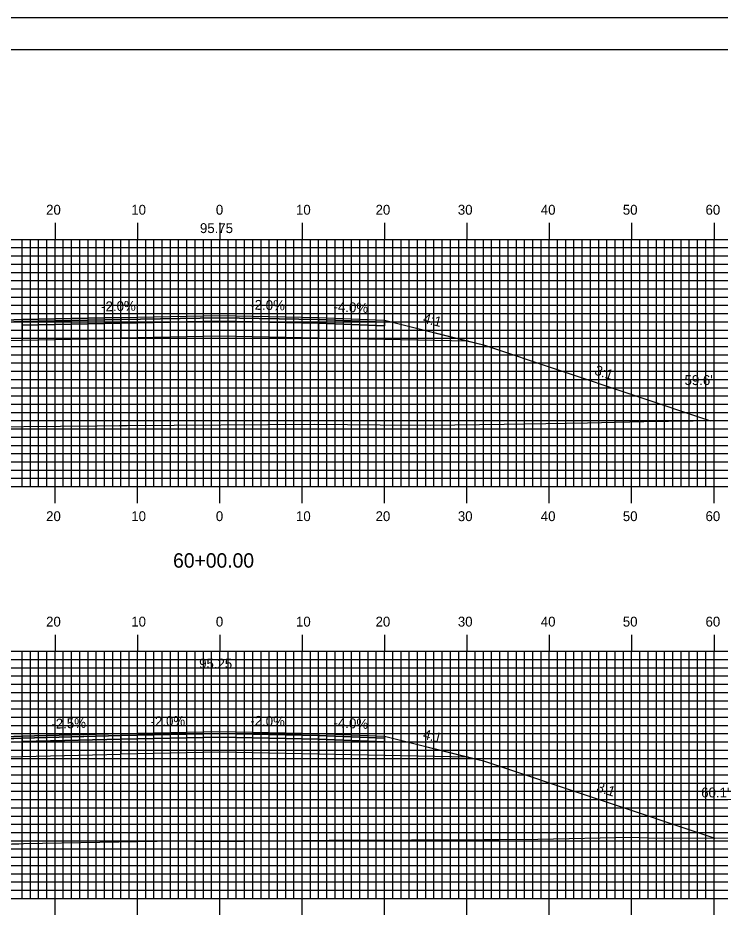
# Model space of a CAD drawing. Extents: x 1757462 to 1757806, y 442591 to 442811.
# Drawn here: x 1757603.6 to 1757689, y 442701.2 to 442810.5 of the extents above; entities that cross this region are included whole.
import ezdxf

# ---------------------------------------------------------------- set-up
doc = ezdxf.new("R2010")
doc.units = 0
for name, color, linetype in [('ANNOTATION', 7, 'Continuous'), ('BORDER', 7, 'Continuous'), ('D_Roadway_Centerline', 7, 'Continuous'), ('D_Roadway_Centerline_Text', 7, 'Continuous'), ('D_Roadway_Edge_Shoulder', 7, 'Continuous'), ('D_Roadway_Edge_TW', 7, 'Continuous'), ('D_Roadway_Pavement', 7, 'Continuous'), ('D_Roadway_SlopeLines', 7, 'Continuous'), ('D_Roadway_SubGrade', 7, 'Continuous'), ('D_Text_Standard', 7, 'Continuous'), ('H_V ANNOTATION', 7, 'Continuous'), ('MAJOR', 7, 'Continuous'), ('MINOR', 7, 'Continuous'), ('PLOT BOUNDARY', 7, 'Continuous'), ('S_Roadway_Centerline', 7, 'Continuous')]:
    doc.layers.add(name, color=color, linetype=linetype)

msp = doc.modelspace()

# ---------------------------------------------------------------- linework, layer by layer
at = {"layer": 'BORDER'}
msp.add_lwpolyline([(1757478.51, 442596.67), (1757798.51, 442596.67), (1757798.51, 442806.67), (1757478.51, 442806.67)], close=True, dxfattribs=at)
at = {"layer": 'D_Roadway_Centerline'}
for points in [[(1757554.49, 442760.74), (1757584.11, 442770.62), (1757585.94, 442771.07), (1757596.11, 442773.62), (1757604.11, 442773.94), (1757616.11, 442774.18), (1757628.11, 442774.42), (1757640.11, 442774.18), (1757648.11, 442773.86), (1757658.28, 442771.31), (1757660.11, 442770.86), (1757687.69, 442761.66)], [(1757552.67, 442709.58), (1757584.11, 442720.06), (1757585.55, 442720.42), (1757596.11, 442723.06), (1757604.11, 442723.38), (1757616.11, 442723.68), (1757628.11, 442723.92), (1757640.11, 442723.68), (1757648.11, 442723.36), (1757658.28, 442720.81), (1757660.11, 442720.36), (1757688.21, 442710.99)]]:
    msp.add_lwpolyline(points, dxfattribs=at)
at = {"layer": 'D_Roadway_Edge_Shoulder'}
for points in [[(1757604.11, 442773.94), (1757596.11, 442773.62), (1757596.11, 442773.37), (1757604.11, 442773.69)], [(1757640.11, 442774.18), (1757648.11, 442773.86), (1757648.11, 442773.61), (1757640.11, 442773.93)], [(1757604.11, 442723.38), (1757596.11, 442723.06), (1757596.11, 442722.81), (1757604.11, 442723.13)], [(1757640.11, 442723.68), (1757648.11, 442723.36), (1757648.11, 442723.11), (1757640.11, 442723.43)]]:
    msp.add_lwpolyline(points, close=True, dxfattribs=at)
at = {"layer": 'D_Roadway_Edge_TW'}
for points in [[(1757616.11, 442773.93), (1757616.11, 442774.18), (1757628.11, 442774.42), (1757640.11, 442774.18), (1757640.11, 442773.93), (1757628.11, 442774.17)], [(1757616.11, 442774.18), (1757604.11, 442773.94), (1757604.11, 442773.69), (1757616.11, 442773.93)], [(1757616.11, 442723.68), (1757604.11, 442723.38), (1757604.11, 442723.13), (1757616.11, 442723.43)], [(1757616.11, 442723.43), (1757616.11, 442723.68), (1757628.11, 442723.92), (1757640.11, 442723.68), (1757640.11, 442723.43), (1757628.11, 442723.67)]]:
    msp.add_lwpolyline(points, close=True, dxfattribs=at)
for points in [[(1757616.11, 442774.18), (1757616.11, 442773.93)], [(1757616.11, 442723.68), (1757616.11, 442723.43)]]:
    msp.add_lwpolyline(points, dxfattribs=at)
at = {"layer": 'D_Roadway_Pavement'}
for points in [[(1757616.11, 442773.93), (1757604.11, 442773.69), (1757604.11, 442773.27), (1757616.11, 442773.51)], [(1757616.11, 442773.51), (1757616.11, 442773.93), (1757628.11, 442774.17), (1757640.11, 442773.93), (1757640.11, 442773.51), (1757628.11, 442773.75)], [(1757640.11, 442773.93), (1757648.11, 442773.61), (1757648.11, 442773.19), (1757640.11, 442773.51)], [(1757616.11, 442723.43), (1757604.11, 442723.13), (1757604.11, 442722.71), (1757616.11, 442723.01)], [(1757616.11, 442723.01), (1757616.11, 442723.43), (1757628.11, 442723.67), (1757640.11, 442723.43), (1757640.11, 442723.01), (1757628.11, 442723.25)], [(1757640.11, 442723.43), (1757648.11, 442723.11), (1757648.11, 442722.69), (1757640.11, 442723.01)]]:
    msp.add_lwpolyline(points, close=True, dxfattribs=at)
for points in [[(1757604.11, 442773.69), (1757604.11, 442773.27)], [(1757616.11, 442773.93), (1757616.11, 442773.51)], [(1757616.11, 442773.93), (1757616.11, 442773.51)], [(1757604.11, 442723.13), (1757604.11, 442722.71)], [(1757616.11, 442723.43), (1757616.11, 442723.01)], [(1757616.11, 442723.43), (1757616.11, 442723.01)]]:
    msp.add_lwpolyline(points, dxfattribs=at)
at = {"layer": 'D_Roadway_SlopeLines'}
for points in [[(1757648.11, 442773.86), (1757660.11, 442770.86), (1757687.69, 442761.66)], [(1757648.11, 442723.36), (1757660.11, 442720.36), (1757688.21, 442710.99)]]:
    msp.add_lwpolyline(points, dxfattribs=at)
at = {"layer": 'D_Roadway_SubGrade'}
for points in [[(1757604.11, 442773.27), (1757604.11, 442773.69), (1757596.11, 442773.37), (1757596.11, 442773.62), (1757585.94, 442771.07), (1757604.11, 442771.44)], [(1757616.11, 442773.51), (1757604.11, 442773.27), (1757604.11, 442771.44), (1757616.11, 442771.68)], [(1757616.11, 442771.68), (1757616.11, 442773.51), (1757628.11, 442773.75), (1757640.11, 442773.51), (1757640.11, 442771.68), (1757628.11, 442771.92)], [(1757640.11, 442773.51), (1757648.11, 442773.19), (1757648.11, 442773.61), (1757648.11, 442773.86), (1757658.28, 442771.31), (1757640.11, 442771.68)], [(1757604.11, 442722.71), (1757604.11, 442723.13), (1757596.11, 442722.81), (1757596.11, 442723.06), (1757585.55, 442720.42), (1757604.11, 442720.88)], [(1757616.11, 442723.01), (1757604.11, 442722.71), (1757604.11, 442720.88), (1757616.11, 442721.18)], [(1757616.11, 442721.18), (1757616.11, 442723.01), (1757628.11, 442723.25), (1757640.11, 442723.01), (1757640.11, 442721.18), (1757628.11, 442721.42)], [(1757640.11, 442723.01), (1757648.11, 442722.69), (1757648.11, 442723.11), (1757648.11, 442723.36), (1757658.28, 442720.81), (1757640.11, 442721.18)]]:
    msp.add_lwpolyline(points, close=True, dxfattribs=at)
for points in [[(1757616.11, 442773.51), (1757616.11, 442771.68)], [(1757616.11, 442723.01), (1757616.11, 442721.18)]]:
    msp.add_lwpolyline(points, dxfattribs=at)
at = {"layer": 'MAJOR'}
for p, q in [((1757608.11, 442785.67), (1757608.11, 442783.67)), ((1757618.11, 442785.67), (1757618.11, 442783.67)), ((1757628.11, 442785.67), (1757628.11, 442783.67)), ((1757638.11, 442785.67), (1757638.11, 442783.67)), ((1757648.11, 442785.67), (1757648.11, 442783.67)), ((1757658.11, 442785.67), (1757658.11, 442783.67)), ((1757668.11, 442785.67), (1757668.11, 442783.67)), ((1757678.11, 442785.67), (1757678.11, 442783.67)), ((1757688.11, 442785.67), (1757688.11, 442783.67)), ((1757488.11, 442783.67), (1757768.11, 442783.67)), ((1757488.11, 442783.67), (1757768.11, 442783.67)), ((1757608.11, 442753.67), (1757608.11, 442783.67)), ((1757618.11, 442753.67), (1757618.11, 442783.67)), ((1757628.11, 442753.67), (1757628.11, 442783.67)), ((1757638.11, 442753.67), (1757638.11, 442783.67)), ((1757648.11, 442753.67), (1757648.11, 442783.67)), ((1757658.11, 442753.67), (1757658.11, 442783.67)), ((1757668.11, 442753.67), (1757668.11, 442783.67)), ((1757678.11, 442753.67), (1757678.11, 442783.67)), ((1757688.11, 442753.67), (1757688.11, 442783.67)), ((1757488.11, 442778.67), (1757768.11, 442778.67)), ((1757488.11, 442773.67), (1757768.11, 442773.67)), ((1757488.11, 442768.67), (1757768.11, 442768.67)), ((1757488.11, 442763.67), (1757768.11, 442763.67)), ((1757488.11, 442758.67), (1757768.11, 442758.67)), ((1757488.11, 442753.67), (1757768.11, 442753.67)), ((1757488.11, 442753.67), (1757768.11, 442753.67)), ((1757608.11, 442751.66), (1757608.11, 442753.67)), ((1757618.11, 442751.66), (1757618.11, 442753.67)), ((1757628.11, 442751.66), (1757628.11, 442753.67)), ((1757638.11, 442751.66), (1757638.11, 442753.67)), ((1757648.11, 442751.66), (1757648.11, 442753.67)), ((1757658.11, 442751.66), (1757658.11, 442753.67)), ((1757668.11, 442751.66), (1757668.11, 442753.67)), ((1757678.11, 442751.66), (1757678.11, 442753.67)), ((1757688.11, 442751.66), (1757688.11, 442753.67)), ((1757608.11, 442735.67), (1757608.11, 442733.67)), ((1757618.11, 442735.67), (1757618.11, 442733.67)), ((1757628.11, 442735.67), (1757628.11, 442733.67)), ((1757638.11, 442735.67), (1757638.11, 442733.67)), ((1757648.11, 442735.67), (1757648.11, 442733.67)), ((1757658.11, 442735.67), (1757658.11, 442733.67)), ((1757668.11, 442735.67), (1757668.11, 442733.67)), ((1757678.11, 442735.67), (1757678.11, 442733.67)), ((1757688.11, 442735.67), (1757688.11, 442733.67)), ((1757488.11, 442733.67), (1757768.11, 442733.67)), ((1757488.11, 442733.67), (1757768.11, 442733.67)), ((1757608.11, 442703.67), (1757608.11, 442733.67)), ((1757618.11, 442703.67), (1757618.11, 442733.67)), ((1757628.11, 442703.67), (1757628.11, 442733.67)), ((1757638.11, 442703.67), (1757638.11, 442733.67)), ((1757648.11, 442703.67), (1757648.11, 442733.67)), ((1757658.11, 442703.67), (1757658.11, 442733.67)), ((1757668.11, 442703.67), (1757668.11, 442733.67)), ((1757678.11, 442703.67), (1757678.11, 442733.67)), ((1757688.11, 442703.67), (1757688.11, 442733.67)), ((1757488.11, 442728.67), (1757768.11, 442728.67)), ((1757488.11, 442723.67), (1757768.11, 442723.67)), ((1757488.11, 442718.67), (1757768.11, 442718.67)), ((1757488.11, 442713.67), (1757768.11, 442713.67)), ((1757488.11, 442708.67), (1757768.11, 442708.67)), ((1757488.11, 442703.67), (1757768.11, 442703.67)), ((1757488.11, 442703.67), (1757768.11, 442703.67)), ((1757608.11, 442701.66), (1757608.11, 442703.67)), ((1757618.11, 442701.66), (1757618.11, 442703.67)), ((1757628.11, 442701.66), (1757628.11, 442703.67)), ((1757638.11, 442701.66), (1757638.11, 442703.67)), ((1757648.11, 442701.66), (1757648.11, 442703.67)), ((1757658.11, 442701.66), (1757658.11, 442703.67)), ((1757668.11, 442701.66), (1757668.11, 442703.67)), ((1757678.11, 442701.66), (1757678.11, 442703.67)), ((1757688.11, 442701.66), (1757688.11, 442703.67))]:
    msp.add_line(p, q, dxfattribs=at)
at = {"layer": 'MINOR'}
for p, q in [((1757604.11, 442753.67), (1757604.11, 442783.67)), ((1757605.11, 442753.67), (1757605.11, 442783.67)), ((1757606.11, 442753.67), (1757606.11, 442783.67)), ((1757607.11, 442753.67), (1757607.11, 442783.67)), ((1757609.11, 442753.67), (1757609.11, 442783.67)), ((1757610.11, 442753.67), (1757610.11, 442783.67)), ((1757611.11, 442753.67), (1757611.11, 442783.67)), ((1757612.11, 442753.67), (1757612.11, 442783.67)), ((1757613.11, 442753.67), (1757613.11, 442783.67)), ((1757614.11, 442753.67), (1757614.11, 442783.67)), ((1757615.11, 442753.67), (1757615.11, 442783.67)), ((1757616.11, 442753.67), (1757616.11, 442783.67)), ((1757617.11, 442753.67), (1757617.11, 442783.67)), ((1757619.11, 442753.67), (1757619.11, 442783.67)), ((1757620.11, 442753.67), (1757620.11, 442783.67)), ((1757621.11, 442753.67), (1757621.11, 442783.67)), ((1757622.11, 442753.67), (1757622.11, 442783.67)), ((1757623.11, 442753.67), (1757623.11, 442783.67)), ((1757624.11, 442753.67), (1757624.11, 442783.67)), ((1757625.11, 442753.67), (1757625.11, 442783.67)), ((1757626.11, 442753.67), (1757626.11, 442783.67)), ((1757627.11, 442753.67), (1757627.11, 442783.67)), ((1757629.11, 442753.67), (1757629.11, 442783.67)), ((1757630.11, 442753.67), (1757630.11, 442783.67)), ((1757631.11, 442753.67), (1757631.11, 442783.67)), ((1757632.11, 442753.67), (1757632.11, 442783.67)), ((1757633.11, 442753.67), (1757633.11, 442783.67)), ((1757634.11, 442753.67), (1757634.11, 442783.67)), ((1757635.11, 442753.67), (1757635.11, 442783.67)), ((1757636.11, 442753.67), (1757636.11, 442783.67)), ((1757637.11, 442753.67), (1757637.11, 442783.67)), ((1757639.11, 442753.67), (1757639.11, 442783.67)), ((1757640.11, 442753.67), (1757640.11, 442783.67)), ((1757641.11, 442753.67), (1757641.11, 442783.67)), ((1757642.11, 442753.67), (1757642.11, 442783.67)), ((1757643.11, 442753.67), (1757643.11, 442783.67)), ((1757644.11, 442753.67), (1757644.11, 442783.67)), ((1757645.11, 442753.67), (1757645.11, 442783.67)), ((1757646.11, 442753.67), (1757646.11, 442783.67)), ((1757647.11, 442753.67), (1757647.11, 442783.67)), ((1757649.11, 442753.67), (1757649.11, 442783.67)), ((1757650.11, 442753.67), (1757650.11, 442783.67)), ((1757651.11, 442753.67), (1757651.11, 442783.67)), ((1757652.11, 442753.67), (1757652.11, 442783.67)), ((1757653.11, 442753.67), (1757653.11, 442783.67)), ((1757654.11, 442753.67), (1757654.11, 442783.67)), ((1757655.11, 442753.67), (1757655.11, 442783.67)), ((1757656.11, 442753.67), (1757656.11, 442783.67)), ((1757657.11, 442753.67), (1757657.11, 442783.67)), ((1757659.11, 442753.67), (1757659.11, 442783.67)), ((1757660.11, 442753.67), (1757660.11, 442783.67)), ((1757661.11, 442753.67), (1757661.11, 442783.67)), ((1757662.11, 442753.67), (1757662.11, 442783.67)), ((1757663.11, 442753.67), (1757663.11, 442783.67)), ((1757664.11, 442753.67), (1757664.11, 442783.67)), ((1757665.11, 442753.67), (1757665.11, 442783.67)), ((1757666.11, 442753.67), (1757666.11, 442783.67)), ((1757667.11, 442753.67), (1757667.11, 442783.67)), ((1757669.11, 442753.67), (1757669.11, 442783.67)), ((1757670.11, 442753.67), (1757670.11, 442783.67)), ((1757671.11, 442753.67), (1757671.11, 442783.67)), ((1757672.11, 442753.67), (1757672.11, 442783.67)), ((1757673.11, 442753.67), (1757673.11, 442783.67)), ((1757674.11, 442753.67), (1757674.11, 442783.67)), ((1757675.11, 442753.67), (1757675.11, 442783.67)), ((1757676.11, 442753.67), (1757676.11, 442783.67)), ((1757677.11, 442753.67), (1757677.11, 442783.67)), ((1757679.11, 442753.67), (1757679.11, 442783.67)), ((1757680.11, 442753.67), (1757680.11, 442783.67)), ((1757681.11, 442753.67), (1757681.11, 442783.67)), ((1757682.11, 442753.67), (1757682.11, 442783.67)), ((1757683.11, 442753.67), (1757683.11, 442783.67)), ((1757684.11, 442753.67), (1757684.11, 442783.67)), ((1757685.11, 442753.67), (1757685.11, 442783.67)), ((1757686.11, 442753.67), (1757686.11, 442783.67)), ((1757687.11, 442753.67), (1757687.11, 442783.67)), ((1757488.11, 442782.67), (1757768.11, 442782.67)), ((1757488.11, 442781.67), (1757768.11, 442781.67)), ((1757488.11, 442780.67), (1757768.11, 442780.67)), ((1757488.11, 442779.67), (1757768.11, 442779.67)), ((1757488.11, 442777.67), (1757768.11, 442777.67)), ((1757488.11, 442776.67), (1757768.11, 442776.67)), ((1757488.11, 442775.67), (1757768.11, 442775.67)), ((1757488.11, 442774.67), (1757768.11, 442774.67)), ((1757488.11, 442772.67), (1757768.11, 442772.67)), ((1757488.11, 442771.67), (1757768.11, 442771.67)), ((1757488.11, 442770.67), (1757768.11, 442770.67)), ((1757488.11, 442769.67), (1757768.11, 442769.67)), ((1757488.11, 442767.67), (1757768.11, 442767.67)), ((1757488.11, 442766.67), (1757768.11, 442766.67)), ((1757488.11, 442765.67), (1757768.11, 442765.67)), ((1757488.11, 442764.67), (1757768.11, 442764.67)), ((1757488.11, 442762.67), (1757768.11, 442762.67)), ((1757488.11, 442761.67), (1757768.11, 442761.67)), ((1757488.11, 442760.67), (1757768.11, 442760.67)), ((1757488.11, 442759.67), (1757768.11, 442759.67)), ((1757488.11, 442757.67), (1757768.11, 442757.67)), ((1757488.11, 442756.67), (1757768.11, 442756.67)), ((1757488.11, 442755.67), (1757768.11, 442755.67)), ((1757488.11, 442754.67), (1757768.11, 442754.67)), ((1757604.11, 442703.67), (1757604.11, 442733.67)), ((1757605.11, 442703.67), (1757605.11, 442733.67)), ((1757606.11, 442703.67), (1757606.11, 442733.67)), ((1757607.11, 442703.67), (1757607.11, 442733.67)), ((1757609.11, 442703.67), (1757609.11, 442733.67)), ((1757610.11, 442703.67), (1757610.11, 442733.67)), ((1757611.11, 442703.67), (1757611.11, 442733.67)), ((1757612.11, 442703.67), (1757612.11, 442733.67)), ((1757613.11, 442703.67), (1757613.11, 442733.67)), ((1757614.11, 442703.67), (1757614.11, 442733.67)), ((1757615.11, 442703.67), (1757615.11, 442733.67)), ((1757616.11, 442703.67), (1757616.11, 442733.67)), ((1757617.11, 442703.67), (1757617.11, 442733.67)), ((1757619.11, 442703.67), (1757619.11, 442733.67)), ((1757620.11, 442703.67), (1757620.11, 442733.67)), ((1757621.11, 442703.67), (1757621.11, 442733.67)), ((1757622.11, 442703.67), (1757622.11, 442733.67)), ((1757623.11, 442703.67), (1757623.11, 442733.67)), ((1757624.11, 442703.67), (1757624.11, 442733.67)), ((1757625.11, 442703.67), (1757625.11, 442733.67)), ((1757626.11, 442703.67), (1757626.11, 442733.67)), ((1757627.11, 442703.67), (1757627.11, 442733.67)), ((1757629.11, 442703.67), (1757629.11, 442733.67)), ((1757630.11, 442703.67), (1757630.11, 442733.67)), ((1757631.11, 442703.67), (1757631.11, 442733.67)), ((1757632.11, 442703.67), (1757632.11, 442733.67)), ((1757633.11, 442703.67), (1757633.11, 442733.67)), ((1757634.11, 442703.67), (1757634.11, 442733.67)), ((1757635.11, 442703.67), (1757635.11, 442733.67)), ((1757636.11, 442703.67), (1757636.11, 442733.67)), ((1757637.11, 442703.67), (1757637.11, 442733.67)), ((1757639.11, 442703.67), (1757639.11, 442733.67)), ((1757640.11, 442703.67), (1757640.11, 442733.67)), ((1757641.11, 442703.67), (1757641.11, 442733.67)), ((1757642.11, 442703.67), (1757642.11, 442733.67)), ((1757643.11, 442703.67), (1757643.11, 442733.67)), ((1757644.11, 442703.67), (1757644.11, 442733.67)), ((1757645.11, 442703.67), (1757645.11, 442733.67)), ((1757646.11, 442703.67), (1757646.11, 442733.67)), ((1757647.11, 442703.67), (1757647.11, 442733.67)), ((1757649.11, 442703.67), (1757649.11, 442733.67)), ((1757650.11, 442703.67), (1757650.11, 442733.67)), ((1757651.11, 442703.67), (1757651.11, 442733.67)), ((1757652.11, 442703.67), (1757652.11, 442733.67)), ((1757653.11, 442703.67), (1757653.11, 442733.67)), ((1757654.11, 442703.67), (1757654.11, 442733.67)), ((1757655.11, 442703.67), (1757655.11, 442733.67)), ((1757656.11, 442703.67), (1757656.11, 442733.67)), ((1757657.11, 442703.67), (1757657.11, 442733.67)), ((1757659.11, 442703.67), (1757659.11, 442733.67)), ((1757660.11, 442703.67), (1757660.11, 442733.67)), ((1757661.11, 442703.67), (1757661.11, 442733.67)), ((1757662.11, 442703.67), (1757662.11, 442733.67)), ((1757663.11, 442703.67), (1757663.11, 442733.67)), ((1757664.11, 442703.67), (1757664.11, 442733.67)), ((1757665.11, 442703.67), (1757665.11, 442733.67)), ((1757666.11, 442703.67), (1757666.11, 442733.67)), ((1757667.11, 442703.67), (1757667.11, 442733.67)), ((1757669.11, 442703.67), (1757669.11, 442733.67)), ((1757670.11, 442703.67), (1757670.11, 442733.67)), ((1757671.11, 442703.67), (1757671.11, 442733.67)), ((1757672.11, 442703.67), (1757672.11, 442733.67)), ((1757673.11, 442703.67), (1757673.11, 442733.67)), ((1757674.11, 442703.67), (1757674.11, 442733.67)), ((1757675.11, 442703.67), (1757675.11, 442733.67)), ((1757676.11, 442703.67), (1757676.11, 442733.67)), ((1757677.11, 442703.67), (1757677.11, 442733.67)), ((1757679.11, 442703.67), (1757679.11, 442733.67)), ((1757680.11, 442703.67), (1757680.11, 442733.67)), ((1757681.11, 442703.67), (1757681.11, 442733.67)), ((1757682.11, 442703.67), (1757682.11, 442733.67)), ((1757683.11, 442703.67), (1757683.11, 442733.67)), ((1757684.11, 442703.67), (1757684.11, 442733.67)), ((1757685.11, 442703.67), (1757685.11, 442733.67)), ((1757686.11, 442703.67), (1757686.11, 442733.67)), ((1757687.11, 442703.67), (1757687.11, 442733.67)), ((1757488.11, 442732.67), (1757768.11, 442732.67)), ((1757488.11, 442731.67), (1757768.11, 442731.67)), ((1757488.11, 442730.67), (1757768.11, 442730.67)), ((1757488.11, 442729.67), (1757768.11, 442729.67)), ((1757488.11, 442727.67), (1757768.11, 442727.67)), ((1757488.11, 442726.67), (1757768.11, 442726.67)), ((1757488.11, 442725.67), (1757768.11, 442725.67)), ((1757488.11, 442724.67), (1757768.11, 442724.67)), ((1757488.11, 442722.67), (1757768.11, 442722.67)), ((1757488.11, 442721.67), (1757768.11, 442721.67)), ((1757488.11, 442720.67), (1757768.11, 442720.67)), ((1757488.11, 442719.67), (1757768.11, 442719.67)), ((1757488.11, 442717.67), (1757768.11, 442717.67)), ((1757488.11, 442716.67), (1757768.11, 442716.67)), ((1757488.11, 442715.67), (1757768.11, 442715.67)), ((1757488.11, 442714.67), (1757768.11, 442714.67)), ((1757488.11, 442712.67), (1757768.11, 442712.67)), ((1757488.11, 442711.67), (1757768.11, 442711.67)), ((1757488.11, 442710.67), (1757768.11, 442710.67)), ((1757488.11, 442709.67), (1757768.11, 442709.67)), ((1757488.11, 442707.67), (1757768.11, 442707.67)), ((1757488.11, 442706.67), (1757768.11, 442706.67)), ((1757488.11, 442705.67), (1757768.11, 442705.67)), ((1757488.11, 442704.67), (1757768.11, 442704.67))]:
    msp.add_line(p, q, dxfattribs=at)
at = {"layer": 'PLOT BOUNDARY'}
msp.add_lwpolyline([(1757462.32, 442590.55), (1757802.32, 442590.55), (1757802.32, 442810.55), (1757462.32, 442810.55)], close=True, dxfattribs=at)
at = {"layer": 'S_Roadway_Centerline'}
for points in [[(1757538.99, 442760.48), (1757544.08, 442760.38), (1757555.91, 442760.79), (1757556.18, 442760.8), (1757556.33, 442760.8), (1757556.95, 442760.8), (1757575.58, 442760.83), (1757584.08, 442760.71), (1757591.1, 442760.5), (1757595.32, 442760.89), (1757613.23, 442761.02), (1757615.91, 442761.08), (1757616.85, 442761.09), (1757639.64, 442761.23), (1757647.56, 442761.15), (1757653.65, 442761.13), (1757662.65, 442761.24), (1757672.74, 442761.41), (1757679.59, 442761.55), (1757691.61, 442761.71)], [(1757488.11, 442708.81), (1757500.51, 442708.88), (1757517.14, 442709.3), (1757522.28, 442709.3), (1757540.34, 442709.4), (1757546.84, 442709.43), (1757549.21, 442709.49), (1757558.21, 442709.71), (1757567.81, 442709.94), (1757582.95, 442709.99), (1757602.84, 442710.29), (1757603.69, 442710.3), (1757604.27, 442710.33), (1757622.81, 442710.66), (1757627.39, 442710.58), (1757634.8, 442710.66), (1757641.39, 442710.72), (1757651.4, 442710.78), (1757660.08, 442710.84), (1757662.16, 442710.84), (1757666.74, 442710.86), (1757678.09, 442711.1), (1757681.09, 442710.97), (1757696.82, 442711.01)]]:
    msp.add_lwpolyline(points, dxfattribs=at)

# ---------------------------------------------------------------- texts
at = {"layer": 'ANNOTATION'}
for s, rotation, p in [('-2.0%', 1.1458, (1757613.72, 442774.93)), ('-2.0%', 358.8542, (1757631.8, 442775.14)), ('-4.0%', 357.7094, (1757641.9, 442774.91)), ('4:1', 345.9638, (1757652.7, 442773.57)), ('3:1', 341.5652, (1757673.51, 442767.3)), ('-2.5%', 1.4217, (1757607.68, 442724.27)), ('-2.0%', 1.1458, (1757619.72, 442724.55)), ('-2.0%', 358.8542, (1757631.8, 442724.64)), ('-4.0%', 357.7094, (1757641.9, 442724.41)), ('4:1', 345.9638, (1757652.7, 442723.07)), ('3:1', 341.5652, (1757673.76, 442716.71))]:
    msp.add_text(s, height=1.2, rotation=rotation, dxfattribs=at).set_placement(p)
at = {"layer": 'D_Roadway_Centerline'}
for s, p in [('C', (1757628.1, 442774.42)), ('L', (1757628.11, 442774.41)), ('C', (1757628.1, 442723.92)), ('L', (1757628.11, 442723.91))]:
    msp.add_text(s, height=0.0146, dxfattribs=at).set_placement(p)
at = {"layer": 'D_Roadway_Centerline_Text'}
for s, p in [('95.75', (1757625.7, 442784.44)), ('95.25', (1757625.6, 442731.58))]:
    msp.add_text(s, height=1.2, dxfattribs=at).set_placement(p)
at = {"layer": 'D_Text_Standard'}
for s, p in [("59.6'", (1757684.53, 442765.99)), ("60.1'", (1757686.55, 442715.93))]:
    msp.add_text(s, height=1.2, dxfattribs=at).set_placement(p)
at = {"layer": 'H_V ANNOTATION'}
for s, height, p in [('20', 1.2, (1757607.02, 442786.67)), ('10', 1.2, (1757617.36, 442786.67)), ('0', 1.2, (1757627.63, 442786.67)), ('10', 1.2, (1757637.36, 442786.67)), ('20', 1.2, (1757647.02, 442786.67)), ('30', 1.2, (1757657.01, 442786.67)), ('40', 1.2, (1757667.08, 442786.67)), ('50', 1.2, (1757677.04, 442786.67)), ('60', 1.2, (1757687.08, 442786.67)), ('20', 1.2, (1757607.02, 442749.47)), ('10', 1.2, (1757617.36, 442749.47)), ('0', 1.2, (1757627.63, 442749.47)), ('10', 1.2, (1757637.36, 442749.47)), ('20', 1.2, (1757647.02, 442749.47)), ('30', 1.2, (1757657.01, 442749.47)), ('40', 1.2, (1757667.08, 442749.47)), ('50', 1.2, (1757677.04, 442749.47)), ('60', 1.2, (1757687.08, 442749.47)), ('60+00.00', 1.75, (1757622.44, 442743.82)), ('20', 1.2, (1757607.02, 442736.67)), ('10', 1.2, (1757617.36, 442736.67)), ('0', 1.2, (1757627.63, 442736.67)), ('10', 1.2, (1757637.36, 442736.67)), ('20', 1.2, (1757647.02, 442736.67)), ('30', 1.2, (1757657.01, 442736.67)), ('40', 1.2, (1757667.08, 442736.67)), ('50', 1.2, (1757677.04, 442736.67)), ('60', 1.2, (1757687.08, 442736.67))]:
    msp.add_text(s, height=height, dxfattribs=at).set_placement(p)

doc.saveas('drawing.dxf')
